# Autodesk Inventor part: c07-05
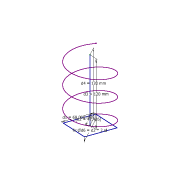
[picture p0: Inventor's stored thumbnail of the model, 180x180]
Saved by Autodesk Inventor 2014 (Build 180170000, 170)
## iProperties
Created: 2010-12
Part Number: c07-05
Material: Generic
Document SubType Name: Modeling
Designer: Thom Tremblay
Density: 1 g/cm^3
Appearance: Generic
Author: Thom Tremblay
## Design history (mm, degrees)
sketch "Sketch1"
  geometry: L1 (30, 30)-(30, -30); L2 (30, -30)-(-30, -30); L3 (-30, -30)-(-30, 30); L4 (-30, 30)-(30, 30); L5 (0, 0)-(30, 30); 1 further point
  constraints: 10 end point, 1 coincident, 1 horizontal, 9 other
  dimensions: "d1" = 60 distance of L3.end L1.start; "d2" = 42.42641 distance of L5.start L1.start (derived)
sketch "Sketch2"
  geometry: L1 (0, 0)-(0, 120)
  constraints: 2 end point, 1 vertical
  dimensions: "d3" = 120 distance of L1.start L1.end
sketch "Guide Path"
  node "Helical Curve1" dims "d4" = 120, "d5" = 30, "d6" = 84.85281 (= 2 x d2), "d7" = 0
